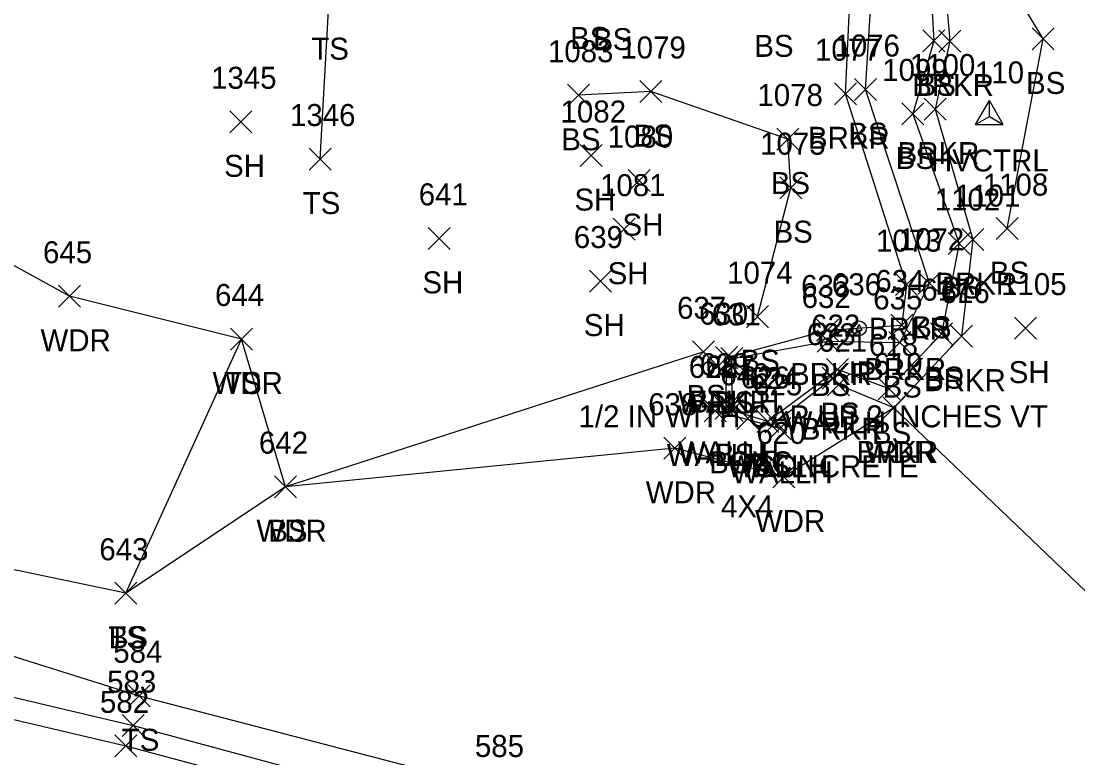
# Model space of a CAD drawing. Extents: x 1485624 to 1495982, y 886445 to 890805.
# Drawn here: x 1495707.4 to 1495803.4, y 890605.4 to 890672.4 of the extents above; entities that cross this region are included whole.
import ezdxf

# ---------------------------------------------------------------- set-up
doc = ezdxf.new("R2010")
doc.units = 0
for name, color, linetype in [('C_A', 7, 'Continuous'), ('C_I', 7, 'Continuous'), ('CPSM', 7, 'Continuous'), ('D_A', 7, 'Continuous'), ('D_C', 7, 'Continuous'), ('D_I', 7, 'Continuous'), ('D_TIC', 7, 'Continuous'), ('DHW', 7, 'Continuous'), ('L_A', 7, 'Continuous'), ('L_I', 7, 'Continuous'), ('L_TIC', 7, 'Continuous'), ('LAWA', 7, 'Continuous'), ('LAWE', 7, 'Continuous'), ('LELB', 7, 'Continuous'), ('M_A', 7, 'Continuous'), ('M_C', 7, 'Continuous'), ('M_I', 7, 'Continuous'), ('MPIR', 7, 'Continuous'), ('P_I', 7, 'Continuous'), ('P_TIC', 7, 'Continuous'), ('PET', 7, 'Continuous'), ('R_I', 7, 'Continuous'), ('R_TIC', 7, 'Continuous'), ('RGR', 7, 'Continuous')]:
    doc.layers.add(name, color=color, linetype=linetype)

msp = doc.modelspace()

# ---------------------------------------------------------------- linework, layer by layer
at = {"layer": 'CPSM'}
for p, q in [((1495794.114, 890662.987), (1495795.364, 890665.152)), ((1495796.614, 890662.987), (1495795.364, 890665.152)), ((1495795.365, 890663.708), (1495795.364, 890665.152)), ((1495794.114, 890662.987), (1495795.365, 890663.708)), ((1495795.365, 890663.708), (1495795.365, 890663.708)), ((1495795.365, 890663.708), (1495796.614, 890662.987)), ((1495794.114, 890662.987), (1495796.614, 890662.987))]:
    msp.add_line(p, q, dxfattribs=at)
at = {"layer": 'D_TIC'}
for points in [[(1495770.478, 890640.793), (1495772.478, 890642.793)], [(1495772.478, 890640.793), (1495770.478, 890642.793)], [(1495780.168, 890638.923), (1495782.168, 890640.923)], [(1495782.168, 890638.923), (1495780.168, 890640.923)], [(1495769.458, 890635.954), (1495771.458, 890637.954)], [(1495771.458, 890635.954), (1495769.458, 890637.954)], [(1495770.459, 890636.201), (1495772.459, 890638.201)], [(1495772.459, 890636.201), (1495770.459, 890638.201)], [(1495772.402, 890635.281), (1495774.402, 890637.281)], [(1495774.402, 890635.281), (1495772.402, 890637.281)], [(1495774.944, 890634.933), (1495776.944, 890636.933)], [(1495776.944, 890634.933), (1495774.944, 890636.933)], [(1495775.31, 890634.364), (1495777.31, 890636.364)], [(1495777.31, 890634.364), (1495775.31, 890636.364)]]:
    msp.add_lwpolyline(points, dxfattribs=at)
at = {"layer": 'DHW'}
for points in [[(1495771.459, 890637.201), (1495771.478, 890641.793)], [(1495781.168, 890639.923), (1495775.944, 890635.933)], [(1495776.31, 890635.364), (1495770.458, 890636.954)]]:
    msp.add_lwpolyline(points, dxfattribs=at)
at = {"layer": 'L_TIC'}
for points in [[(1495789.311, 890669.581), (1495791.311, 890671.581)], [(1495791.311, 890669.581), (1495789.311, 890671.581)], [(1495790.759, 890669.552), (1495792.759, 890671.552)], [(1495792.759, 890669.552), (1495790.759, 890671.552)], [(1495799.254, 890669.753), (1495801.254, 890671.753)], [(1495801.254, 890669.753), (1495799.254, 890671.753)], [(1495757.023, 890664.635), (1495759.023, 890666.635)], [(1495759.023, 890664.635), (1495757.023, 890666.635)], [(1495763.602, 890664.974), (1495765.602, 890666.974)], [(1495765.602, 890664.974), (1495763.602, 890666.974)], [(1495781.288, 890664.768), (1495783.288, 890666.768)], [(1495783.288, 890664.768), (1495781.288, 890666.768)], [(1495783.109, 890665.151), (1495785.109, 890667.151)], [(1495785.109, 890665.151), (1495783.109, 890667.151)], [(1495787.406, 890662.935), (1495789.406, 890664.935)], [(1495789.406, 890662.935), (1495787.406, 890664.935)], [(1495789.428, 890663.377), (1495791.428, 890665.377)], [(1495791.428, 890663.377), (1495789.428, 890665.377)], [(1495726.332, 890662.222), (1495728.332, 890664.222)], [(1495728.332, 890662.222), (1495726.332, 890664.222)], [(1495776.056, 890660.655), (1495778.056, 890662.655)], [(1495778.056, 890660.655), (1495776.056, 890662.655)], [(1495733.557, 890658.839), (1495735.557, 890660.839)], [(1495735.557, 890658.839), (1495733.557, 890660.839)], [(1495758.171, 890659.157), (1495760.171, 890661.157)], [(1495760.171, 890659.157), (1495758.171, 890661.157)], [(1495762.533, 890656.878), (1495764.533, 890658.878)], [(1495764.533, 890656.878), (1495762.533, 890658.878)], [(1495776.308, 890656.236), (1495778.308, 890658.236)], [(1495778.308, 890656.236), (1495776.308, 890658.236)], [(1495761.19, 890652.467), (1495763.19, 890654.467)], [(1495763.19, 890652.467), (1495761.19, 890654.467)], [(1495795.97, 890652.515), (1495797.97, 890654.515)], [(1495797.97, 890652.515), (1495795.97, 890654.515)], [(1495744.354, 890651.632), (1495746.354, 890653.632)], [(1495746.354, 890651.632), (1495744.354, 890653.632)], [(1495791.61, 890651.165), (1495793.61, 890653.165)], [(1495793.61, 890651.165), (1495791.61, 890653.165)], [(1495792.866, 890651.52), (1495794.866, 890653.52)], [(1495794.866, 890651.52), (1495792.866, 890653.52)], [(1495759.02, 890647.752), (1495761.02, 890649.752)], [(1495761.02, 890647.752), (1495759.02, 890649.752)], [(1495786.828, 890647.427), (1495788.828, 890649.427)], [(1495788.828, 890647.427), (1495786.828, 890649.427)], [(1495788.907, 890647.554), (1495790.907, 890649.554)], [(1495790.907, 890647.554), (1495788.907, 890649.554)], [(1495710.777, 890646.374), (1495712.777, 890648.374)], [(1495712.777, 890646.374), (1495710.777, 890648.374)], [(1495773.303, 890644.518), (1495775.303, 890646.518)], [(1495775.303, 890644.518), (1495773.303, 890646.518)], [(1495786.409, 890643.759), (1495788.409, 890645.759)], [(1495788.409, 890643.759), (1495786.409, 890645.759)], [(1495797.634, 890643.477), (1495799.634, 890645.477)], [(1495799.634, 890643.477), (1495797.634, 890645.477)], [(1495726.408, 890642.487), (1495728.408, 890644.487)], [(1495728.408, 890642.487), (1495726.408, 890644.487)], [(1495726.408, 890642.487), (1495728.408, 890644.487)], [(1495728.408, 890642.487), (1495726.408, 890644.487)], [(1495779.663, 890643.301), (1495781.663, 890645.301)], [(1495781.663, 890643.301), (1495779.663, 890645.301)], [(1495790.019, 890642.971), (1495792.019, 890644.971)], [(1495792.019, 890642.971), (1495790.019, 890644.971)], [(1495791.833, 890642.749), (1495793.833, 890644.749)], [(1495793.833, 890642.749), (1495791.833, 890644.749)], [(1495779.71, 890642.306), (1495781.71, 890644.306)], [(1495781.71, 890642.306), (1495779.71, 890644.306)], [(1495786.218, 890642.165), (1495788.218, 890644.165)], [(1495788.218, 890642.165), (1495786.218, 890644.165)], [(1495768.396, 890641.322), (1495770.396, 890643.322)], [(1495770.396, 890641.322), (1495768.396, 890643.322)], [(1495770.478, 890640.793), (1495772.478, 890642.793)], [(1495772.478, 890640.793), (1495770.478, 890642.793)], [(1495770.971, 890640.72), (1495772.971, 890642.72)], [(1495772.971, 890640.72), (1495770.971, 890642.72)], [(1495780.574, 890639.708), (1495782.574, 890641.708)], [(1495782.574, 890639.708), (1495780.574, 890641.708)], [(1495780.639, 890638.336), (1495782.639, 890640.336)], [(1495782.639, 890638.336), (1495780.639, 890640.336)], [(1495785.258, 890637.958), (1495787.258, 890639.958)], [(1495787.258, 890637.958), (1495785.258, 890639.958)], [(1495770.992, 890635.985), (1495772.992, 890637.985)], [(1495772.992, 890635.985), (1495770.992, 890637.985)], [(1495785.691, 890636.227), (1495787.691, 890638.227)], [(1495787.691, 890636.227), (1495785.691, 890638.227)], [(1495785.691, 890636.227), (1495787.691, 890638.227)], [(1495787.691, 890636.227), (1495785.691, 890638.227)], [(1495774.233, 890634.996), (1495776.233, 890636.996)], [(1495776.233, 890634.996), (1495774.233, 890636.996)], [(1495765.773, 890632.561), (1495767.773, 890634.561)], [(1495767.773, 890632.561), (1495765.773, 890634.561)], [(1495775.7, 890629.955), (1495777.7, 890631.955)], [(1495777.7, 890629.955), (1495775.7, 890631.955)], [(1495730.397, 890629.071), (1495732.397, 890631.071)], [(1495732.397, 890629.071), (1495730.397, 890631.071)], [(1495730.397, 890629.071), (1495732.397, 890631.071)], [(1495732.397, 890629.071), (1495730.397, 890631.071)], [(1495715.893, 890619.387), (1495717.893, 890621.387)], [(1495717.893, 890619.387), (1495715.893, 890621.387)], [(1495715.893, 890619.387), (1495717.893, 890621.387)], [(1495717.893, 890619.387), (1495715.893, 890621.387)], [(1495717.113, 890610.074), (1495719.113, 890612.074)], [(1495719.113, 890610.074), (1495717.113, 890612.074)]]:
    msp.add_lwpolyline(points, dxfattribs=at)
at = {"layer": 'LAWA'}
msp.add_lwpolyline([(1495871.713, 890600.371), (1495857.998, 890600.353), (1495826.66, 890611.452), (1495806.153, 890618.61), (1495786.691, 890637.227), (1495776.7, 890630.955), (1495766.773, 890633.561), (1495731.397, 890630.071), (1495727.408, 890643.487), (1495711.777, 890647.374), (1495680.109, 890664.791)], dxfattribs=at)
at = {"layer": 'LAWE'}
for points in [[(1495787.828, 890648.427), (1495782.288, 890665.768), (1495782.959, 890680.05), (1495785.272, 890693.321), (1495790.597, 890684.405), (1495791.759, 890670.552), (1495790.428, 890664.377), (1495793.866, 890652.52)], [(1495793.866, 890652.52), (1495792.833, 890643.749)], [(1495787.828, 890648.427), (1495787.409, 890644.759)], [(1495771.478, 890641.793), (1495780.663, 890644.301), (1495787.409, 890644.759)], [(1495792.833, 890643.749), (1495786.691, 890637.227), (1495781.639, 890639.336)]]:
    msp.add_lwpolyline(points, dxfattribs=at)
at = {"layer": 'LELB'}
for points in [[(1495789.907, 890648.554), (1495784.109, 890666.151), (1495784.985, 890680.176), (1495787.965, 890691.878)], [(1495796.97, 890653.515), (1495800.254, 890670.753), (1495795.134, 890679.276), (1495800.61, 890689.514)], [(1495734.557, 890659.839), (1495735.335, 890673.866), (1495727.583, 890678.095), (1495719.915, 890684.026)], [(1495789.509, 890684.643), (1495790.311, 890670.581), (1495788.406, 890663.935), (1495792.61, 890652.165)], [(1495774.303, 890645.518), (1495777.308, 890657.236), (1495777.056, 890661.655), (1495764.602, 890665.974), (1495758.023, 890665.635)], [(1495792.61, 890652.165), (1495791.019, 890643.971)], [(1495769.396, 890642.322), (1495731.397, 890630.071), (1495716.893, 890620.387), (1495698.906, 890624.147), (1495663.565, 890638.21), (1495629.563, 890649.097)], [(1495789.907, 890648.554), (1495787.218, 890643.165)], [(1495617.507, 890647.423), (1495659.254, 890631.909), (1495662.576, 890630.344), (1495680.117, 890622.998), (1495718.113, 890611.074), (1495750.976, 890602.511), (1495783.183, 890591.684), (1495810.937, 890582.068), (1495845.909, 890568.148), (1495889.077, 890548.909)], [(1495716.893, 890620.387), (1495727.408, 890643.487)], [(1495791.019, 890643.971), (1495786.258, 890638.958), (1495781.574, 890640.708), (1495775.233, 890635.996), (1495771.992, 890636.985), (1495771.971, 890641.72), (1495780.71, 890643.306), (1495787.218, 890643.165)]]:
    msp.add_lwpolyline(points, dxfattribs=at)
at = {"layer": 'MPIR'}
msp.add_lwpolyline([(1495783.519, 890644.794), (1495783.23, 890644.294), (1495783.808, 890644.294)], close=True, dxfattribs=at)
msp.add_circle((1495783.519, 890644.46), 0.667, dxfattribs=at)
at = {"layer": 'P_TIC'}
for points in [[(1495715.905, 890605.52), (1495717.905, 890607.52)], [(1495717.905, 890605.52), (1495715.905, 890607.52)]]:
    msp.add_lwpolyline(points, dxfattribs=at)
at = {"layer": 'PET'}
msp.add_lwpolyline([(1495609.581, 890624.88), (1495650.016, 890621.06), (1495682.445, 890614.598), (1495716.905, 890606.52), (1495749.593, 890597.755), (1495779.952, 890588.139), (1495810.503, 890576.957), (1495842.996, 890563.527), (1495882.776, 890545.006)], dxfattribs=at)
at = {"layer": 'R_TIC'}
for points in [[(1495716.554, 890607.366), (1495718.554, 890609.366)], [(1495718.554, 890607.366), (1495716.554, 890609.366)]]:
    msp.add_lwpolyline(points, dxfattribs=at)
at = {"layer": 'RGR'}
msp.add_lwpolyline([(1495657.987, 890625.638), (1495670.774, 890620.075), (1495682.613, 890616.631), (1495717.554, 890608.366), (1495750.399, 890599.503), (1495781.031, 890589.568), (1495810.951, 890578.473), (1495843.968, 890564.673), (1495884.044, 890546.25), (1495911.226, 890532.904), (1495928.251, 890525.82), (1495941.85, 890522.119)], dxfattribs=at)

# ---------------------------------------------------------------- texts
at = {"layer": 'C_A'}
msp.add_text('HVCTRL', height=2, dxfattribs=at).set_placement((1495790.058, 890658.708))
at = {"layer": 'C_I'}
msp.add_text('110', height=2, dxfattribs=at).set_placement((1495794.05, 890666.708))
at = {"layer": 'D_A'}
for s, p in [('WALLH', (1495767.069, 890636.793)), ('WALLH', (1495776.759, 890634.923)), ('WALLH', (1495766.048, 890631.954)), ('WALLH', (1495767.049, 890632.201)), ('BOXC', (1495769.898, 890631.281)), ('WALLH', (1495771.534, 890630.933)), ('WALLH', (1495771.9, 890630.364))]:
    msp.add_text(s, height=2, dxfattribs=at).set_placement(p)
at = {"layer": 'D_C'}
for s, p in [('CONCRETE', (1495773.924, 890630.923)), ('4X4', (1495770.977, 890627.281))]:
    msp.add_text(s, height=2, dxfattribs=at).set_placement(p)
at = {"layer": 'D_I'}
for s, p in [('630', (1495768.982, 890644.793)), ('623', (1495778.759, 890642.923)), ('628', (1495768.048, 890639.954)), ('629', (1495769.041, 890640.201)), ('640', (1495770.906, 890639.281)), ('624', (1495773.534, 890638.933)), ('625', (1495773.9, 890638.364))]:
    msp.add_text(s, height=2, dxfattribs=at).set_placement(p)
at = {"layer": 'L_A'}
for s, p in [('BS', (1495757.269, 890669.842)), ('BS', (1495759.348, 890669.731)), ('TS', (1495733.744, 890668.866)), ('BS', (1495774.003, 890669.123)), ('BRKR', (1495788.35, 890665.552)), ('BS', (1495788.752, 890665.581)), ('BS', (1495798.695, 890665.753)), ('BS', (1495756.464, 890660.635)), ('BS', (1495763.043, 890660.974)), ('BRKR', (1495778.879, 890660.768)), ('BS', (1495782.55, 890661.151)), ('BS', (1495786.847, 890658.935)), ('BRKR', (1495787.019, 890659.377)), ('SH', (1495725.82, 890658.222)), ('BS', (1495775.497, 890656.655)), ('SH', (1495757.659, 890655.157)), ('TS', (1495732.967, 890654.839)), ('SH', (1495762.021, 890652.878)), ('BS', (1495775.749, 890652.236)), ('SH', (1495760.678, 890648.467)), ('BS', (1495795.411, 890648.515)), ('SH', (1495743.842, 890647.632)), ('BRKR', (1495790.457, 890647.52)), ('BS', (1495791.051, 890647.165)), ('SH', (1495758.509, 890643.752)), ('BRKR', (1495784.419, 890643.427)), ('BS', (1495788.348, 890643.554)), ('WDR', (1495709.139, 890642.374)), ('BS', (1495772.744, 890640.518)), ('BRKR', (1495784, 890639.759)), ('BRKR', (1495777.254, 890639.301)), ('BRKR', (1495789.423, 890638.749)), ('BS', (1495789.46, 890638.971)), ('SH', (1495797.122, 890639.477)), ('WDR', (1495724.771, 890638.487)), ('TS', (1495725.818, 890638.487)), ('BS', (1495779.151, 890638.306)), ('BS', (1495785.659, 890638.165)), ('BS', (1495767.837, 890637.322)), ('BRKR', (1495768.069, 890636.793)), ('BS', (1495770.412, 890636.72)), ('BS', (1495780.015, 890635.708)), ('BRKR', (1495778.23, 890634.336)), ('BS', (1495784.699, 890633.958)), ('BS', (1495770.433, 890631.985)), ('BRKR', (1495783.282, 890632.227)), ('WDR', (1495784.053, 890632.227)), ('BS', (1495773.674, 890630.996)), ('WDR', (1495764.135, 890628.561)), ('WDR', (1495774.062, 890625.955)), ('WDR', (1495728.759, 890625.071)), ('BS', (1495729.838, 890625.071)), ('TS', (1495715.303, 890615.387)), ('BS', (1495715.334, 890615.387)), ('TS', (1495716.522, 890606.074))]:
    msp.add_text(s, height=2, dxfattribs=at).set_placement(p)
at = {"layer": 'L_I'}
for s, p in [('1083', (1495755.252, 890668.635)), ('1079', (1495761.823, 890668.974)), ('1077', (1495779.517, 890668.768)), ('1076', (1495781.282, 890669.151)), ('1100', (1495788.137, 890667.377)), ('1099', (1495785.627, 890666.935)), ('1345', (1495724.639, 890666.222)), ('1078', (1495774.285, 890664.655)), ('1346', (1495731.81, 890662.839)), ('1082', (1495756.399, 890663.157)), ('1080', (1495760.675, 890660.878)), ('1075', (1495774.536, 890660.236)), ('1081', (1495759.985, 890656.467)), ('1108', (1495794.765, 890656.515)), ('641', (1495743.511, 890655.632)), ('1102', (1495790.405, 890655.165)), ('1101', (1495792.229, 890655.52)), ('639', (1495757.603, 890651.752)), ('1073', (1495785.057, 890651.427)), ('1072', (1495787.135, 890651.554)), ('645', (1495709.367, 890650.374)), ('1074', (1495771.531, 890648.518)), ('633', (1495778.254, 890647.301)), ('634', (1495785, 890647.759)), ('1105', (1495796.429, 890647.477)), ('644', (1495724.999, 890646.487)), ('644', (1495724.999, 890646.487)), ('632', (1495778.301, 890646.306)), ('617', (1495789.176, 890646.971)), ('616', (1495790.935, 890646.749)), ('637', (1495766.987, 890645.322)), ('635', (1495784.808, 890646.165)), ('630', (1495768.982, 890644.793)), ('631', (1495770.128, 890644.72)), ('622', (1495779.165, 890643.708)), ('621', (1495779.797, 890642.336)), ('618', (1495784.415, 890641.958)), ('627', (1495769.583, 890639.985)), ('619', (1495784.841, 890640.227)), ('619', (1495784.841, 890640.227)), ('626', (1495772.768, 890638.996)), ('638', (1495764.363, 890636.561)), ('620', (1495774.204, 890633.955)), ('642', (1495728.987, 890633.071)), ('642', (1495728.987, 890633.071)), ('643', (1495714.484, 890623.387)), ('643', (1495714.484, 890623.387)), ('584', (1495715.75, 890614.074)), ('585', (1495748.614, 890605.511))]:
    msp.add_text(s, height=2, dxfattribs=at).set_placement(p)
at = {"layer": 'M_A'}
msp.add_text('IP', height=2, dxfattribs=at).set_placement((1495782.566, 890639.46))
at = {"layer": 'M_C'}
msp.add_text('1/2 IN WITH CAP UP 2 INCHES VT', height=2, dxfattribs=at).set_placement((1495758.032, 890635.46))
at = {"layer": 'M_I'}
msp.add_text('636', height=2, dxfattribs=at).set_placement((1495781.054, 890647.46))
at = {"layer": 'P_I'}
msp.add_text('582', height=2, dxfattribs=at).set_placement((1495714.542, 890609.52))
at = {"layer": 'R_I'}
msp.add_text('583', height=2, dxfattribs=at).set_placement((1495715.192, 890611.366))

doc.saveas('drawing.dxf')
